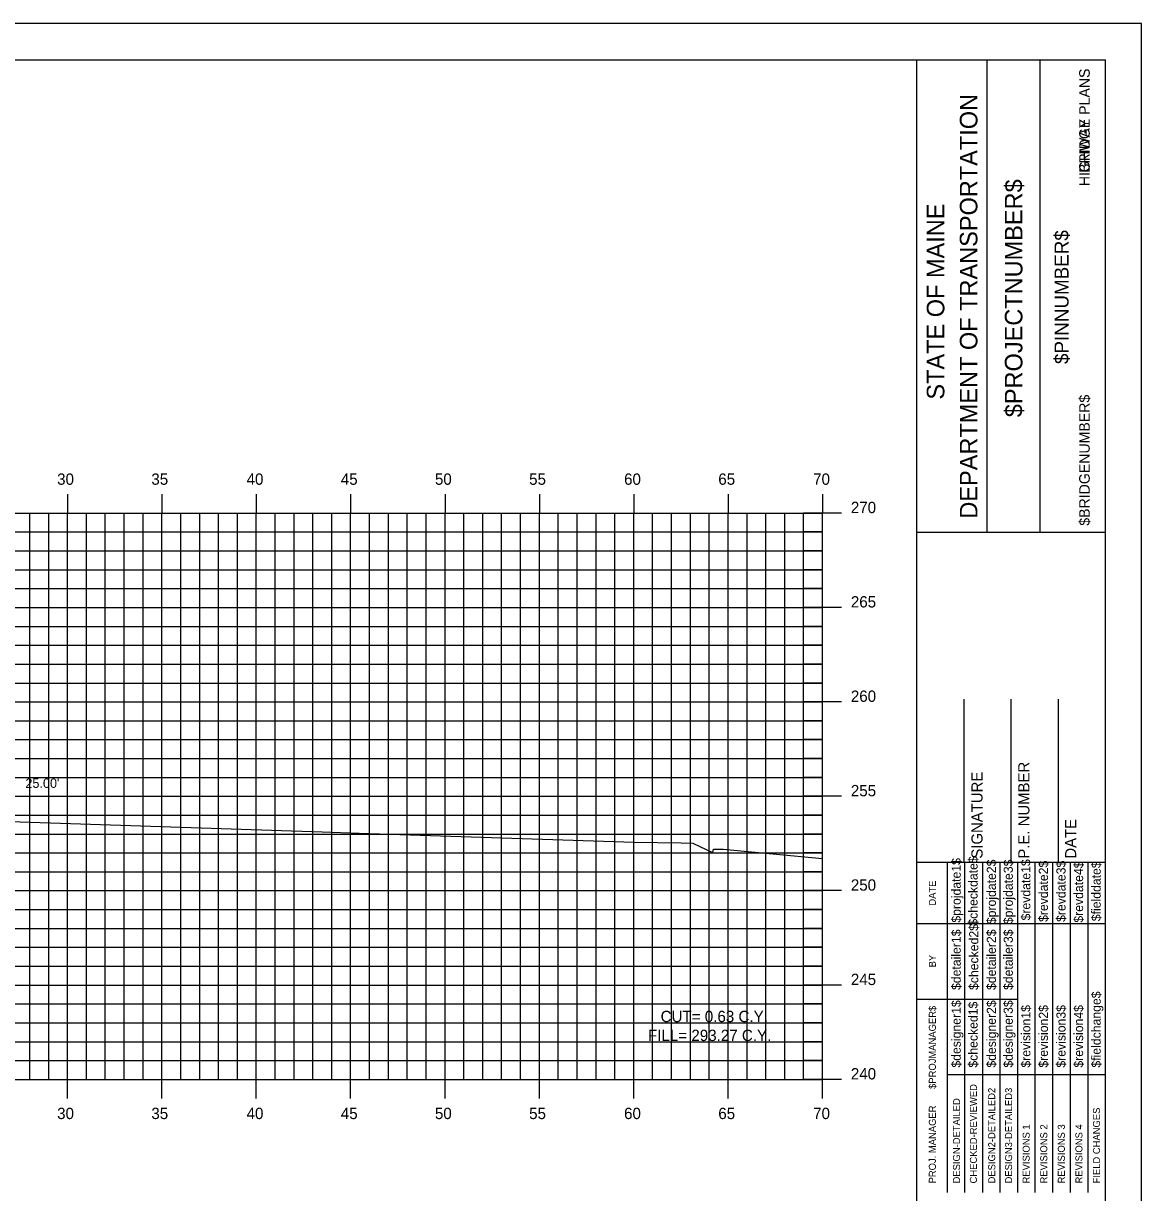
# Model space of a CAD drawing. Extents: x 1170543 to 1177585, y 609599 to 610623.
# Drawn here: x 1175384.7 to 1175444, y 609646.9 to 609708.8 of the extents above; entities that cross this region are included whole.
import ezdxf

# ---------------------------------------------------------------- set-up
doc = ezdxf.new("R2010")
doc.units = 0
for name, color, linetype in [('ANNOTATION', 7, 'Continuous'), ('BORDER', 7, 'Continuous'), ('BRIDGE_TITLE', 7, 'Continuous'), ('D_Roadway_Centerline_Text', 7, 'Continuous'), ('H_V ANNOTATION', 7, 'Continuous'), ('HIGHWAY_TITLE', 7, 'Continuous'), ('MAJOR', 7, 'Continuous'), ('MINOR', 7, 'Continuous'), ('PLOT BOUNDARY', 7, 'Continuous'), ('S_Roadway_Centerline', 7, 'Continuous')]:
    doc.layers.add(name, color=color, linetype=linetype)

msp = doc.modelspace()

# ---------------------------------------------------------------- linework, layer by layer
at = {"layer": 'BORDER'}
for p, q in [((1175442.07, 609706.872), (1175282.07, 609706.872)), ((1175432.07, 609601.875), (1175432.07, 609706.875)), ((1175435.798, 609681.869), (1175435.798, 609706.869)), ((1175438.593, 609681.869), (1175438.593, 609706.869)), ((1175442.07, 609601.875), (1175442.07, 609706.875)), ((1175432.071, 609681.866), (1175442.07, 609681.866)), ((1175434.57, 609664.375), (1175434.57, 609673.023)), ((1175437.07, 609664.375), (1175437.07, 609673.023)), ((1175439.57, 609664.375), (1175439.57, 609673.023)), ((1175432.07, 609664.375), (1175442.07, 609664.375))]:
    msp.add_line(p, q, dxfattribs=at)
for points in [[(1175433.685, 609661.125), (1175433.685, 609664.375)], [(1175434.617, 609646.878), (1175434.617, 609664.375)], [(1175435.549, 609664.375), (1175435.549, 609646.878)], [(1175436.481, 609646.878), (1175436.481, 609664.375)], [(1175437.412, 609646.878), (1175437.412, 609664.375)], [(1175438.344, 609646.878), (1175438.344, 609664.375)], [(1175439.276, 609646.878), (1175439.276, 609664.375)], [(1175440.207, 609646.878), (1175440.207, 609664.375)], [(1175441.139, 609646.878), (1175441.139, 609664.375)], [(1175433.686, 609646.878), (1175433.686, 609663.669)], [(1175432.07, 609661.125), (1175442.07, 609661.125)], [(1175432.07, 609657.125), (1175433.686, 609657.125)], [(1175433.685, 609657.125), (1175437.411, 609657.125)], [(1175433.685, 609653.125), (1175442.07, 609653.125)]]:
    msp.add_lwpolyline(points, dxfattribs=at)
at = {"layer": 'MAJOR'}
for p, q in [((1175387.07, 609683.874), (1175387.07, 609682.872)), ((1175392.07, 609683.874), (1175392.07, 609682.872)), ((1175397.07, 609683.874), (1175397.07, 609682.872)), ((1175402.07, 609683.874), (1175402.07, 609682.872)), ((1175407.07, 609683.874), (1175407.07, 609682.872)), ((1175412.07, 609683.874), (1175412.07, 609682.872)), ((1175417.07, 609683.874), (1175417.07, 609682.872)), ((1175422.07, 609683.874), (1175422.07, 609682.872)), ((1175427.07, 609683.874), (1175427.07, 609682.872)), ((1175287.07, 609682.872), (1175427.07, 609682.872)), ((1175287.07, 609682.872), (1175427.07, 609682.872)), ((1175387.07, 609652.872), (1175387.07, 609682.872)), ((1175392.07, 609652.872), (1175392.07, 609682.872)), ((1175397.07, 609652.872), (1175397.07, 609682.872)), ((1175402.07, 609652.872), (1175402.07, 609682.872)), ((1175407.07, 609652.872), (1175407.07, 609682.872)), ((1175412.07, 609652.872), (1175412.07, 609682.872)), ((1175417.07, 609652.872), (1175417.07, 609682.872)), ((1175422.07, 609652.872), (1175422.07, 609682.872)), ((1175428.072, 609682.872), (1175426.068, 609682.872)), ((1175427.07, 609652.872), (1175427.07, 609682.872)), ((1175427.07, 609652.872), (1175427.07, 609682.872)), ((1175287.07, 609677.872), (1175427.07, 609677.872)), ((1175428.072, 609677.872), (1175426.068, 609677.872)), ((1175287.07, 609672.872), (1175427.07, 609672.872)), ((1175428.072, 609672.872), (1175426.068, 609672.872)), ((1175287.07, 609667.872), (1175427.07, 609667.872)), ((1175428.072, 609667.872), (1175426.068, 609667.872)), ((1175287.07, 609662.872), (1175427.07, 609662.872)), ((1175428.072, 609662.872), (1175426.068, 609662.872)), ((1175287.07, 609657.872), (1175427.07, 609657.872)), ((1175428.072, 609657.872), (1175426.068, 609657.872)), ((1175287.07, 609652.872), (1175427.07, 609652.872)), ((1175287.07, 609652.872), (1175427.07, 609652.872)), ((1175387.07, 609651.87), (1175387.07, 609652.872)), ((1175392.07, 609651.87), (1175392.07, 609652.872)), ((1175397.07, 609651.87), (1175397.07, 609652.872)), ((1175402.07, 609651.87), (1175402.07, 609652.872)), ((1175407.07, 609651.87), (1175407.07, 609652.872)), ((1175412.07, 609651.87), (1175412.07, 609652.872)), ((1175417.07, 609651.87), (1175417.07, 609652.872)), ((1175422.07, 609651.87), (1175422.07, 609652.872)), ((1175428.072, 609652.872), (1175426.068, 609652.872)), ((1175427.07, 609651.87), (1175427.07, 609652.872))]:
    msp.add_line(p, q, dxfattribs=at)
at = {"layer": 'MINOR'}
for p, q in [((1175385.07, 609652.872), (1175385.07, 609682.872)), ((1175386.07, 609652.872), (1175386.07, 609682.872)), ((1175388.07, 609652.872), (1175388.07, 609682.872)), ((1175389.07, 609652.872), (1175389.07, 609682.872)), ((1175390.07, 609652.872), (1175390.07, 609682.872)), ((1175391.07, 609652.872), (1175391.07, 609682.872)), ((1175393.07, 609652.872), (1175393.07, 609682.872)), ((1175394.07, 609652.872), (1175394.07, 609682.872)), ((1175395.07, 609652.872), (1175395.07, 609682.872)), ((1175396.07, 609652.872), (1175396.07, 609682.872)), ((1175398.07, 609652.872), (1175398.07, 609682.872)), ((1175399.07, 609652.872), (1175399.07, 609682.872)), ((1175400.07, 609652.872), (1175400.07, 609682.872)), ((1175401.07, 609652.872), (1175401.07, 609682.872)), ((1175403.07, 609652.872), (1175403.07, 609682.872)), ((1175404.07, 609652.872), (1175404.07, 609682.872)), ((1175405.07, 609652.872), (1175405.07, 609682.872)), ((1175406.07, 609652.872), (1175406.07, 609682.872)), ((1175408.07, 609652.872), (1175408.07, 609682.872)), ((1175409.07, 609652.872), (1175409.07, 609682.872)), ((1175410.07, 609652.872), (1175410.07, 609682.872)), ((1175411.07, 609652.872), (1175411.07, 609682.872)), ((1175413.07, 609652.872), (1175413.07, 609682.872)), ((1175414.07, 609652.872), (1175414.07, 609682.872)), ((1175415.07, 609652.872), (1175415.07, 609682.872)), ((1175416.07, 609652.872), (1175416.07, 609682.872)), ((1175418.07, 609652.872), (1175418.07, 609682.872)), ((1175419.07, 609652.872), (1175419.07, 609682.872)), ((1175420.07, 609652.872), (1175420.07, 609682.872)), ((1175421.07, 609652.872), (1175421.07, 609682.872)), ((1175423.07, 609652.872), (1175423.07, 609682.872)), ((1175424.07, 609652.872), (1175424.07, 609682.872)), ((1175425.07, 609652.872), (1175425.07, 609682.872)), ((1175426.07, 609652.872), (1175426.07, 609682.872)), ((1175287.07, 609681.872), (1175427.07, 609681.872)), ((1175427.07, 609681.872), (1175426.068, 609681.872)), ((1175287.07, 609680.872), (1175427.07, 609680.872)), ((1175427.07, 609680.872), (1175426.068, 609680.872)), ((1175287.07, 609679.872), (1175427.07, 609679.872)), ((1175427.07, 609679.872), (1175426.068, 609679.872)), ((1175287.07, 609678.872), (1175427.07, 609678.872)), ((1175427.07, 609678.872), (1175426.068, 609678.872)), ((1175287.07, 609676.872), (1175427.07, 609676.872)), ((1175427.07, 609676.872), (1175426.068, 609676.872)), ((1175287.07, 609675.872), (1175427.07, 609675.872)), ((1175427.07, 609675.872), (1175426.068, 609675.872)), ((1175287.07, 609674.872), (1175427.07, 609674.872)), ((1175427.07, 609674.872), (1175426.068, 609674.872)), ((1175287.07, 609673.872), (1175427.07, 609673.872)), ((1175427.07, 609673.872), (1175426.068, 609673.872)), ((1175287.07, 609671.872), (1175427.07, 609671.872)), ((1175427.07, 609671.872), (1175426.068, 609671.872)), ((1175287.07, 609670.872), (1175427.07, 609670.872)), ((1175427.07, 609670.872), (1175426.068, 609670.872)), ((1175287.07, 609669.872), (1175427.07, 609669.872)), ((1175427.07, 609669.872), (1175426.068, 609669.872)), ((1175287.07, 609668.872), (1175427.07, 609668.872)), ((1175427.07, 609668.872), (1175426.068, 609668.872)), ((1175287.07, 609666.872), (1175427.07, 609666.872)), ((1175427.07, 609666.872), (1175426.068, 609666.872)), ((1175287.07, 609665.872), (1175427.07, 609665.872)), ((1175427.07, 609665.872), (1175426.068, 609665.872)), ((1175287.07, 609664.872), (1175427.07, 609664.872)), ((1175427.07, 609664.872), (1175426.068, 609664.872)), ((1175287.07, 609663.872), (1175427.07, 609663.872)), ((1175427.07, 609663.872), (1175426.068, 609663.872)), ((1175287.07, 609661.872), (1175427.07, 609661.872)), ((1175427.07, 609661.872), (1175426.068, 609661.872)), ((1175287.07, 609660.872), (1175427.07, 609660.872)), ((1175427.07, 609660.872), (1175426.068, 609660.872)), ((1175287.07, 609659.872), (1175427.07, 609659.872)), ((1175427.07, 609659.872), (1175426.068, 609659.872)), ((1175287.07, 609658.872), (1175427.07, 609658.872)), ((1175427.07, 609658.872), (1175426.068, 609658.872)), ((1175287.07, 609656.872), (1175427.07, 609656.872)), ((1175427.07, 609656.872), (1175426.068, 609656.872)), ((1175287.07, 609655.872), (1175427.07, 609655.872)), ((1175427.07, 609655.872), (1175426.068, 609655.872)), ((1175287.07, 609654.872), (1175427.07, 609654.872)), ((1175427.07, 609654.872), (1175426.068, 609654.872)), ((1175287.07, 609653.872), (1175427.07, 609653.872)), ((1175427.07, 609653.872), (1175426.068, 609653.872))]:
    msp.add_line(p, q, dxfattribs=at)
at = {"layer": 'PLOT BOUNDARY'}
msp.add_lwpolyline([(1175273.976, 609598.813), (1175443.976, 609598.813), (1175443.976, 609708.813), (1175273.976, 609708.813)], close=True, dxfattribs=at)
at = {"layer": 'S_Roadway_Centerline'}
msp.add_lwpolyline([(1175384.032, 609666.528), (1175398.928, 609666.036), (1175400.566, 609665.982), (1175402.513, 609665.919), (1175417.099, 609665.437), (1175419.575, 609665.403), (1175420.199, 609665.395), (1175420.235, 609665.378), (1175421.238, 609664.898), (1175421.256, 609664.888), (1175421.289, 609665.077), (1175421.814, 609665.066), (1175427.07, 609664.581)], dxfattribs=at)

# ---------------------------------------------------------------- texts
at = {"layer": 'ANNOTATION'}
msp.add_text("25.00'", height=0.5, dxfattribs=at).set_placement((1175384.838, 609668.315))
at = {"layer": 'BORDER'}
for s, height, p in [('DEPARTMENT OF TRANSPORTATION', 0.93176, (1175435.277, 609682.578)), ('$PROJECTNUMBER$', 0.93176, (1175437.662, 609687.951)), ('STATE OF MAINE', 0.93176, (1175433.525, 609688.884)), ('$PINNUMBER$', 0.74527, (1175440.107, 609690.769)), ('P.E. NUMBER', 0.59055, (1175438.031, 609664.567)), ('SIGNATURE', 0.5906, (1175435.55, 609664.567)), ('DATE', 0.5906, (1175440.511, 609664.567)), ('$projdate1$', 0.48455, (1175434.393, 609661.176)), ('$checkdate$', 0.48455, (1175435.287, 609661.018)), ('$projdate2$', 0.48455, (1175436.256, 609661.097)), ('$projdate3$', 0.48455, (1175437.151, 609661.097)), ('$revdate1$', 0.4845, (1175438.082, 609661.294)), ('$revdate2$', 0.4845, (1175439.014, 609661.215)), ('$revdate3$', 0.4845, (1175439.946, 609661.215)), ('$revdate4$', 0.4845, (1175440.877, 609661.176)), ('$fielddate$', 0.48455, (1175441.809, 609661.254)), ('DATE', 0.3714, (1175433.074, 609662.081)), ('$detailer1$', 0.48455, (1175434.393, 609657.61)), ('$checked2$', 0.4845, (1175435.324, 609657.61)), ('$detailer2$', 0.48455, (1175436.256, 609657.61)), ('$detailer3$', 0.48455, (1175437.151, 609657.61)), ('BY', 0.3714, (1175433.074, 609658.81)), ('$fieldchange$', 0.48455, (1175441.809, 609653.498)), ('$PROJMANAGER$', 0.37275, (1175433.074, 609652.37)), ('$designer1$', 0.48455, (1175434.393, 609653.498)), ('$checked1$', 0.4845, (1175435.287, 609653.498)), ('$designer2$', 0.48455, (1175436.256, 609653.498)), ('$designer3$', 0.48455, (1175437.151, 609653.498)), ('$revision1$', 0.48455, (1175438.082, 609653.498)), ('$revision2$', 0.48455, (1175439.014, 609653.498)), ('$revision3$', 0.48455, (1175439.946, 609653.498)), ('$revision4$', 0.48455, (1175440.877, 609653.498)), ('CHECKED-REVIEWED', 0.37275, (1175435.251, 609647.363)), ('DESIGN-DETAILED', 0.37275, (1175434.356, 609647.363)), ('DESIGN2-DETAILED2', 0.37275, (1175436.22, 609647.363)), ('DESIGN3-DETAILED3', 0.37275, (1175437.114, 609647.363)), ('PROJ. MANAGER', 0.37275, (1175433.074, 609647.363)), ('FIELD CHANGES', 0.37275, (1175441.773, 609647.363)), ('REVISIONS 1', 0.37275, (1175438.046, 609647.363)), ('REVISIONS 2', 0.37275, (1175438.978, 609647.363)), ('REVISIONS 3', 0.37275, (1175439.909, 609647.363)), ('REVISIONS 4', 0.37275, (1175440.841, 609647.363))]:
    msp.add_text(s, height=height, rotation=90, dxfattribs=at).set_placement(p)
at = {"layer": 'BRIDGE_TITLE'}
for s, p in [('BRIDGE PLANS', (1175441.228, 609700.897)), ('$BRIDGENUMBER$', (1175441.228, 609682.203))]:
    msp.add_text(s, height=0.55901, rotation=90, dxfattribs=at).set_placement(p)
at = {"layer": 'D_Roadway_Centerline_Text'}
for s, p in [('CUT= 0.63 C.Y.', (1175418.492, 609655.908)), ('FILL= 293.27 C.Y.', (1175417.824, 609654.906))]:
    msp.add_text(s, height=0.6, dxfattribs=at).set_placement(p)
at = {"layer": 'H_V ANNOTATION'}
for s, p in [('30', (1175386.518, 609684.372)), ('35', (1175391.51, 609684.372)), ('40', (1175396.556, 609684.372)), ('45', (1175401.548, 609684.372)), ('50', (1175406.534, 609684.372)), ('55', (1175411.526, 609684.372)), ('60', (1175416.556, 609684.372)), ('65', (1175421.548, 609684.372)), ('70', (1175426.572, 609684.372)), ('270', (1175428.57, 609682.872)), ('265', (1175428.57, 609677.872)), ('260', (1175428.57, 609672.872)), ('255', (1175428.57, 609667.872)), ('250', (1175428.57, 609662.872)), ('245', (1175428.57, 609657.872)), ('240', (1175428.57, 609652.872)), ('30', (1175386.518, 609650.772)), ('35', (1175391.51, 609650.772)), ('40', (1175396.556, 609650.772)), ('45', (1175401.548, 609650.772)), ('50', (1175406.534, 609650.772)), ('55', (1175411.526, 609650.772)), ('60', (1175416.556, 609650.772)), ('65', (1175421.548, 609650.772)), ('70', (1175426.572, 609650.772))]:
    msp.add_text(s, height=0.6, dxfattribs=at).set_placement(p)
at = {"layer": 'HIGHWAY_TITLE'}
msp.add_text('HIGHWAY PLANS', height=0.55901, rotation=90, dxfattribs=at).set_placement((1175441.228, 609700.188))

doc.saveas('drawing.dxf')
